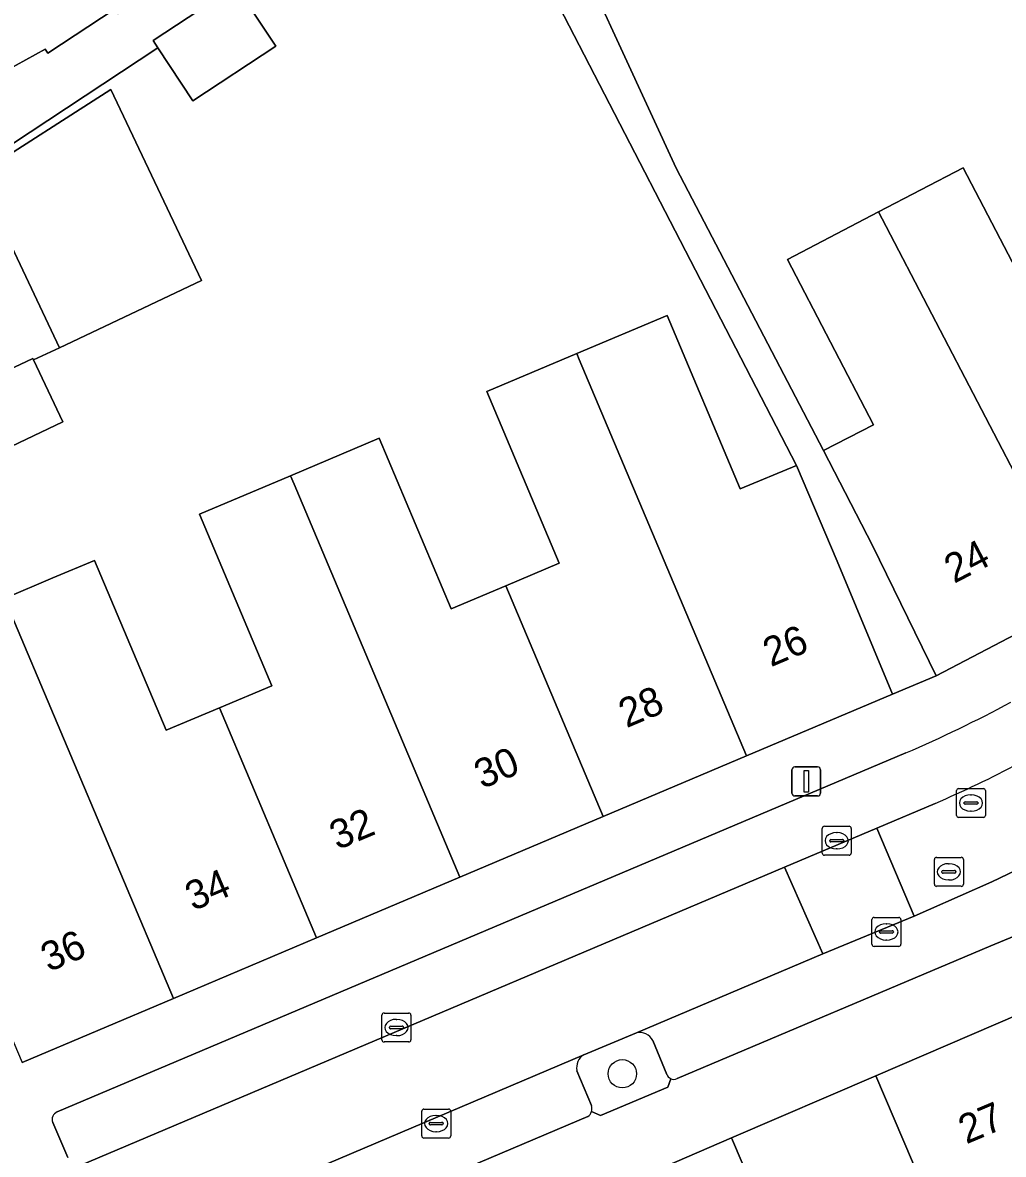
# Model space of a CAD drawing. Extents: x 159716 to 160783, y 383290 to 384031.
# Drawn here: x 160412.95 to 160446.78, y 383462.26 to 383501.29 of the extents above; entities that cross this region are included whole.
import ezdxf

# ---------------------------------------------------------------- set-up
doc = ezdxf.new("R2010")
doc.units = 0
for name, color, linetype in [('IMGEO_Boom', 7, 'Continuous'), ('IMGEO_Erf', 7, 'Continuous'), ('IMGEO_Groenvoorziening', 7, 'Continuous'), ('IMGEO_Kolk', 7, 'Continuous'), ('IMGEO_Lichtmast', 7, 'Continuous'), ('IMGEO_Pand', 7, 'Continuous'), ('IMGEO_Pand_nummerreeks', 7, 'Continuous'), ('IMGEO_Parkeervlak_open', 7, 'Continuous'), ('IMGEO_Rijbaan_lokaal_open', 7, 'Continuous'), ('IMGEO_Rioolput', 7, 'Continuous'), ('IMGEO_Voetpad_open', 7, 'Continuous')]:
    doc.layers.add(name, color=color, linetype=linetype)

msp = doc.modelspace()

# ---------------------------------------------------------------- linework, layer by layer
at = {"layer": 'IMGEO_Boom'}
msp.add_circle((160433.635, 383465.037), 0.489, dxfattribs=at)
at = {"layer": 'IMGEO_Erf'}
for points in [[(160410.053, 383498.348), (160413.731, 383500.37), (160413.822, 383500.233), (160416.145, 383501.77), (160414.883, 383503.676), (160417.563, 383505.448), (160418.824, 383503.542), (160419.035, 383503.681), (160420.163, 383504.383), (160417.766, 383508.006), (160420.889, 383510.072), (160422.04, 383508.332), (160424.811, 383510.165), (160426.163, 383508.121), (160426.24, 383508.005), (160429.356, 383510.045), (160428.037, 383512.04), (160430.525, 383513.686), (160434.534, 383516.338), (160435.854, 383514.343), (160436.792, 383514.858), (160423.195, 383534.022)], [(160430.856, 383506.328), (160435.49, 383496.267), (160440.572, 383486.539), (160442.3, 383487.42), (160439.33, 383493.124), (160442.476, 383494.762), (160445.394, 383496.282), (160448.357, 383490.591), (160450.214, 383491.558), (160451.942, 383492.458), (160448.967, 383498.17), (160452.021, 383499.746), (160452.513, 383500), (160454.934, 383501.249), (160455.587, 383500), (160457.9, 383495.572), (160459.761, 383496.541), (160461.074, 383497.224), (160458.07, 383502.859)], [(160412.323, 383481.431), (160413.995, 383482.137), (160415.428, 383482.742), (160417.902, 383476.883), (160419.742, 383477.66), (160421.544, 383478.421), (160419.047, 383484.335), (160422.19, 383485.662), (160425.252, 383486.955), (160427.734, 383481.076), (160429.617, 383481.871), (160431.455, 383482.647), (160428.958, 383488.563), (160432.064, 383489.875), (160435.177, 383491.189), (160437.698, 383485.217), (160439.641, 383486.018), (160429.533, 383505.571)], [(160420.299, 383502.563), (160421.679, 383500.478), (160418.827, 383498.592), (160417.613, 383500.427), (160411.306, 383496.264)], [(160411.39, 383496.045), (160415.995, 383498.988), (160419.12, 383492.397), (160414.221, 383490.074), (160413.329, 383489.658), (160414.343, 383487.52), (160410.518, 383485.706)]]:
    msp.add_lwpolyline(points, dxfattribs=at)
at = {"layer": 'IMGEO_Groenvoorziening'}
for points in [[(160434.119, 383466.447), (160432.306, 383465.692)], [(160435.166, 383465.011), (160434.69, 383466.181)], [(160432.07, 383465.144), (160432.575, 383463.94)], [(160432.572, 383463.735), (160432.884, 383463.6), (160435.203, 383464.573), (160435.303, 383464.868)]]:
    msp.add_lwpolyline(points, dxfattribs=at)
for centre, radius, start, end in [((160434.233, 383465.945), 0.515, 27.2902, 102.7529), ((160432.575, 383465.252), 0.516, 121.3704, 192.0307), ((160435.413, 383465.111), 0.266, 201.9501, 245.5948), ((160432.242, 383463.842), 0.347, 341.9589, 16.3642)]:
    msp.add_arc(centre, radius, start, end, dxfattribs=at)
at = {"layer": 'IMGEO_Kolk'}
for p, q in [((160440.529, 383472.649), (160440.529, 383473.501)), ((160440.604, 383473.575), (160441.456, 383473.575)), ((160441.53, 383473.501), (160441.53, 383472.649)), ((160440.788, 383473.069), (160440.788, 383473.081)), ((160440.831, 383473.118), (160441.229, 383473.118)), ((160441.017, 383473.355), (160441.042, 383473.355)), ((160441.272, 383473.081), (160441.272, 383473.069)), ((160441.226, 383473.032), (160440.828, 383473.032)), ((160441.04, 383472.795), (160441.015, 383472.795)), ((160441.456, 383472.575), (160440.604, 383472.575)), ((160442.242, 383469.503), (160442.242, 383470.355)), ((160442.317, 383470.429), (160443.169, 383470.429)), ((160443.243, 383470.355), (160443.243, 383469.503)), ((160442.544, 383469.972), (160442.942, 383469.972)), ((160442.73, 383470.209), (160442.755, 383470.209)), ((160442.501, 383469.923), (160442.501, 383469.935)), ((160442.939, 383469.886), (160442.541, 383469.886)), ((160442.753, 383469.649), (160442.728, 383469.649)), ((160442.985, 383469.935), (160442.985, 383469.923)), ((160443.169, 383469.429), (160442.317, 383469.429)), ((160425.344, 383466.207), (160425.344, 383467.059)), ((160425.419, 383467.133), (160426.271, 383467.133)), ((160425.832, 383466.913), (160425.857, 383466.913)), ((160426.345, 383467.059), (160426.345, 383466.207)), ((160425.603, 383466.627), (160425.603, 383466.639)), ((160426.041, 383466.59), (160425.643, 383466.59)), ((160425.646, 383466.676), (160426.044, 383466.676)), ((160426.087, 383466.639), (160426.087, 383466.627)), ((160426.271, 383466.133), (160425.419, 383466.133)), ((160425.855, 383466.353), (160425.83, 383466.353)), ((160426.715, 383462.893), (160426.715, 383463.745)), ((160426.79, 383463.819), (160427.642, 383463.819)), ((160427.716, 383463.745), (160427.716, 383462.893)), ((160426.974, 383463.313), (160426.974, 383463.325)), ((160427.017, 383463.362), (160427.415, 383463.362)), ((160427.203, 383463.599), (160427.228, 383463.599)), ((160427.458, 383463.325), (160427.458, 383463.313)), ((160427.412, 383463.276), (160427.014, 383463.276)), ((160427.226, 383463.039), (160427.201, 383463.039)), ((160427.642, 383462.819), (160426.79, 383462.819))]:
    msp.add_line(p, q, dxfattribs=at)
for points in [[(160440.529, 383472.649), (160440.529, 383473.501)], [(160440.604, 383473.575), (160441.456, 383473.575)], [(160441.53, 383473.501), (160441.53, 383472.649)], [(160441.456, 383472.575), (160440.604, 383472.575)], [(160442.242, 383469.503), (160442.242, 383470.355)], [(160442.317, 383470.429), (160443.169, 383470.429)], [(160443.243, 383470.355), (160443.243, 383469.503)], [(160443.169, 383469.429), (160442.317, 383469.429)], [(160425.344, 383466.207), (160425.344, 383467.059)], [(160425.419, 383467.133), (160426.271, 383467.133)], [(160426.345, 383467.059), (160426.345, 383466.207)], [(160426.271, 383466.133), (160425.419, 383466.133)], [(160426.715, 383462.893), (160426.715, 383463.745)], [(160426.79, 383463.819), (160427.642, 383463.819)], [(160427.716, 383463.745), (160427.716, 383462.893)], [(160427.642, 383462.819), (160426.79, 383462.819)]]:
    msp.add_lwpolyline(points, dxfattribs=at)
for centre, radius, start, end in [((160440.606, 383473.499), 0.0765, 91.552, 178.448), ((160440.606, 383473.499), 0.0765, 91.552, 178.448), ((160441.454, 383473.499), 0.0765, 1.552, 88.448), ((160441.454, 383473.499), 0.0765, 1.552, 88.448), ((160440.828, 383473.078), 0.0403, 85.8775, 175.7526), ((160441.233, 383473.08), 0.0386, 1.7309, 96.639), ((160440.825, 383473.068), 0.0366, 178.938, 274.7102), ((160441.229, 383473.075), 0.043, 264.8664, 352.4533), ((160440.606, 383472.651), 0.0765, 181.552, 268.448), ((160440.606, 383472.651), 0.0765, 181.552, 268.448), ((160441.454, 383472.651), 0.0765, 271.552, 358.448), ((160441.454, 383472.651), 0.0765, 271.552, 358.448), ((160442.319, 383470.353), 0.0765, 91.552, 178.448), ((160442.319, 383470.353), 0.0765, 91.552, 178.448), ((160443.167, 383470.353), 0.0765, 1.552, 88.448), ((160443.167, 383470.353), 0.0765, 1.552, 88.448), ((160442.541, 383469.932), 0.0403, 85.8775, 175.7526), ((160442.946, 383469.934), 0.0386, 1.7309, 96.639), ((160442.538, 383469.922), 0.0366, 178.938, 274.7102), ((160442.942, 383469.929), 0.043, 264.8664, 352.4533), ((160442.319, 383469.505), 0.0765, 181.552, 268.448), ((160442.319, 383469.505), 0.0765, 181.552, 268.448), ((160443.167, 383469.505), 0.0765, 271.552, 358.448), ((160443.167, 383469.505), 0.0765, 271.552, 358.448), ((160425.421, 383467.057), 0.0765, 91.552, 178.448), ((160425.421, 383467.057), 0.0765, 91.552, 178.448), ((160426.269, 383467.057), 0.0765, 1.552, 88.448), ((160426.269, 383467.057), 0.0765, 1.552, 88.448), ((160425.643, 383466.636), 0.0403, 85.8775, 175.7526), ((160425.64, 383466.626), 0.0366, 178.938, 274.7102), ((160426.044, 383466.633), 0.043, 264.8664, 352.4533), ((160426.048, 383466.638), 0.0386, 1.7309, 96.639), ((160425.421, 383466.209), 0.0765, 181.552, 268.448), ((160425.421, 383466.209), 0.0765, 181.552, 268.448), ((160426.269, 383466.209), 0.0765, 271.552, 358.448), ((160426.269, 383466.209), 0.0765, 271.552, 358.448), ((160426.792, 383463.743), 0.0765, 91.552, 178.448), ((160426.792, 383463.743), 0.0765, 91.552, 178.448), ((160427.64, 383463.743), 0.0765, 1.552, 88.448), ((160427.64, 383463.743), 0.0765, 1.552, 88.448), ((160427.014, 383463.322), 0.0403, 85.8775, 175.7526), ((160427.419, 383463.324), 0.0386, 1.7309, 96.639), ((160427.011, 383463.312), 0.0366, 178.938, 274.7102), ((160427.415, 383463.319), 0.043, 264.8664, 352.4533), ((160426.792, 383462.895), 0.0765, 181.552, 268.448), ((160426.792, 383462.895), 0.0765, 181.552, 268.448), ((160427.64, 383462.895), 0.0765, 271.552, 358.448), ((160427.64, 383462.895), 0.0765, 271.552, 358.448)]:
    msp.add_arc(centre, radius, start, end, dxfattribs=at)
for centre, major_axis, ratio, start_param, end_param in [((160441.016, 383473.075), (-0.387, 0.002), 0.722429, 4.712389, 7.853982), ((160441.041, 383473.075), (-0.39, 0.002), 0.717154, 1.570796, 4.712389), ((160442.729, 383469.929), (-0.387, 0.002), 0.722429, 4.712389, 7.853982), ((160442.754, 383469.929), (-0.39, 0.002), 0.717154, 1.570796, 4.712389), ((160425.831, 383466.633), (-0.387, 0.002), 0.722429, 4.712389, 7.853982), ((160425.856, 383466.633), (-0.39, 0.002), 0.717154, 1.570796, 4.712389), ((160427.202, 383463.319), (-0.387, 0.002), 0.722429, 4.712389, 7.853982), ((160427.227, 383463.319), (-0.39, 0.002), 0.717154, 1.570796, 4.712389)]:
    msp.add_ellipse(centre, major_axis=major_axis, ratio=ratio, start_param=start_param, end_param=end_param, dxfattribs=at)
at = {"layer": 'IMGEO_Lichtmast'}
for p, q in [((160439.481, 383474.719), (160439.481, 383475.519)), ((160439.481, 383475.519), (160439.481, 383474.719)), ((160439.581, 383475.619), (160440.371, 383475.619)), ((160440.371, 383475.619), (160439.581, 383475.619)), ((160440.471, 383475.519), (160440.471, 383474.719)), ((160440.471, 383474.719), (160440.471, 383475.519)), ((160440.371, 383474.619), (160439.581, 383474.619)), ((160439.581, 383474.619), (160440.371, 383474.619))]:
    msp.add_line(p, q, dxfattribs=at)
msp.add_lwpolyline([(160439.901, 383475.494), (160440.051, 383475.494), (160440.051, 383474.744), (160439.901, 383474.744), (160439.901, 383475.494)], dxfattribs=at)
for centre, start, end in [((160439.581, 383475.519), 90, 180), ((160439.581, 383475.519), 90, 180), ((160440.371, 383475.519), 0, 90), ((160440.371, 383475.519), 360, 90), ((160439.581, 383474.719), 180, 270), ((160439.581, 383474.719), 180, 270), ((160440.371, 383474.719), 270, 0), ((160440.371, 383474.719), 270, 0)]:
    msp.add_arc(centre, 0.1, start, end, dxfattribs=at)
at = {"layer": 'IMGEO_Pand'}
for points in [[(160420.299, 383502.563), (160417.448, 383500.677), (160417.613, 383500.427), (160418.827, 383498.592), (160421.679, 383500.478)], [(160411.39, 383496.045), (160414.221, 383490.074), (160419.12, 383492.397), (160415.995, 383498.988)], [(160450.214, 383491.558), (160448.357, 383490.591), (160445.394, 383496.282), (160442.476, 383494.762), (160442.599, 383494.526), (160449.448, 383481.371), (160454.219, 383483.867)], [(160442.599, 383494.526), (160442.476, 383494.762), (160439.33, 383493.124), (160442.3, 383487.42), (160440.572, 383486.539), (160442.259, 383483.26), (160444.456, 383478.761), (160449.448, 383481.371)], [(160439.641, 383486.018), (160437.698, 383485.217), (160435.177, 383491.189), (160432.064, 383489.875), (160432.152, 383489.667), (160437.922, 383476.001), (160442.949, 383478.128), (160441.044, 383482.714)], [(160432.152, 383489.667), (160432.064, 383489.875), (160428.958, 383488.563), (160431.455, 383482.647), (160429.617, 383481.871), (160432.979, 383473.909), (160437.922, 383476.001)], [(160413.329, 383489.658), (160413.304, 383489.711), (160409.479, 383487.897), (160410.518, 383485.706), (160414.343, 383487.52)], [(160429.617, 383481.871), (160427.734, 383481.076), (160425.252, 383486.955), (160422.19, 383485.662), (160422.314, 383485.368), (160428.035, 383471.817), (160432.979, 383473.909)], [(160422.314, 383485.368), (160422.19, 383485.662), (160419.047, 383484.335), (160421.544, 383478.421), (160419.742, 383477.66), (160423.092, 383469.726), (160428.035, 383471.817)], [(160419.742, 383477.66), (160417.902, 383476.883), (160415.428, 383482.742), (160413.995, 383482.137), (160412.323, 383481.431), (160418.149, 383467.634), (160423.092, 383469.726)], [(160412.323, 383481.431), (160409.388, 383480.191), (160411.839, 383474.387), (160409.537, 383473.422), (160412.932, 383465.426), (160418.149, 383467.634)], [(160447.343, 383467.106), (160442.373, 383464.964), (160445.87, 383456.765), (160447.814, 383457.594), (160450.146, 383452.125), (160453.18, 383453.418)], [(160442.373, 383464.964), (160437.405, 383462.822), (160443.225, 383449.175), (160446.457, 383450.553), (160444.125, 383456.021), (160445.87, 383456.765)], [(160437.405, 383462.822), (160432.435, 383460.679), (160435.948, 383452.441), (160437.943, 383453.292), (160440.272, 383447.829), (160443.256, 383449.102), (160443.225, 383449.175)]]:
    msp.add_lwpolyline(points, close=True, dxfattribs=at)
at = {"layer": 'IMGEO_Parkeervlak_open'}
for points in [[(160443.414, 383476.101), (160414.146, 383463.719)], [(160414.256, 383461.59), (160439.234, 383472.166), (160442.414, 383473.513), (160444.425, 383474.364)], [(160450.686, 383473.825), (160448.326, 383472.59), (160446.383, 383471.66), (160444.194, 383470.688), (160443.698, 383470.478), (160440.546, 383469.169), (160434.119, 383466.447)], [(160435.53, 383464.871), (160446.34, 383469.449), (160447.487, 383469.926), (160448.781, 383470.565), (160450.997, 383471.726)], [(160434.69, 383466.181), (160435.166, 383465.011)], [(160432.306, 383465.692), (160420.476, 383460.662)], [(160432.575, 383463.94), (160432.07, 383465.144)], [(160413.989, 383463.356), (160414.506, 383462.153)], [(160421.908, 383459.097), (160432.448, 383463.559)]]:
    msp.add_lwpolyline(points, dxfattribs=at)
for centre, radius, start, end in [((160423.943, 383521.012), 48.95, 293.4389, 298.1502), ((160427.937, 383512.547), 41.591, 293.3559, 297.778), ((160434.233, 383465.945), 0.515, 27.2902, 102.7529), ((160432.575, 383465.252), 0.516, 121.3704, 192.0307), ((160435.413, 383465.111), 0.266, 201.9501, 245.5948), ((160435.413, 383465.109), 0.265, 245.4303, 296.084), ((160414.244, 383463.461), 0.276, 110.8719, 202.3504), ((160432.242, 383463.836), 0.345, 306.673, 342.9941), ((160432.242, 383463.842), 0.347, 341.9589, 16.3642)]:
    msp.add_arc(centre, radius, start, end, dxfattribs=at)
at = {"layer": 'IMGEO_Rijbaan_lokaal_open'}
msp.add_lwpolyline([(160444.425, 383474.364), (160442.414, 383473.513), (160443.698, 383470.478), (160444.194, 383470.688), (160446.383, 383471.66), (160448.326, 383472.59), (160450.686, 383473.825), (160452.428, 383474.705), (160468.689, 383483.205), (160470.424, 383484.097), (160475.827, 383486.951), (160477.633, 383487.98), (160479.723, 383489.166), (160486.172, 383493.171)], dxfattribs=at)
for points in [[(160442.414, 383473.513), (160439.234, 383472.166), (160440.546, 383469.169), (160443.698, 383470.478)], [(160413.413, 383457.726), (160414.355, 383458.079), (160415.032, 383458.338), (160419.59, 383460.282), (160420.476, 383460.662), (160432.306, 383465.692), (160434.119, 383466.447), (160440.546, 383469.169), (160439.234, 383472.166), (160414.256, 383461.59), (160411.383, 383460.426), (160408.637, 383459.367), (160406.976, 383458.771), (160391.978, 383453.269), (160378.421, 383448.278), (160373.951, 383446.647), (160375.101, 383443.604), (160376.222, 383444.022), (160377.682, 383444.533), (160394.918, 383450.857), (160396.309, 383451.338)]]:
    msp.add_lwpolyline(points, close=True, dxfattribs=at)
msp.add_arc((160427.937, 383512.547), 41.591, 293.3559, 297.778, dxfattribs=at)
at = {"layer": 'IMGEO_Rioolput'}
for p, q in [((160445.16, 383473.95), (160445.16, 383474.802)), ((160445.235, 383474.876), (160446.087, 383474.876)), ((160445.648, 383474.656), (160445.673, 383474.656)), ((160446.161, 383474.802), (160446.161, 383473.95)), ((160445.419, 383474.37), (160445.419, 383474.382)), ((160445.857, 383474.333), (160445.459, 383474.333)), ((160445.462, 383474.419), (160445.86, 383474.419)), ((160445.903, 383474.382), (160445.903, 383474.37)), ((160446.087, 383473.876), (160445.235, 383473.876)), ((160445.671, 383474.096), (160445.646, 383474.096)), ((160444.397, 383471.576), (160444.397, 383472.428)), ((160444.472, 383472.502), (160445.324, 383472.502)), ((160445.398, 383472.428), (160445.398, 383471.576)), ((160444.656, 383471.996), (160444.656, 383472.008)), ((160445.094, 383471.959), (160444.696, 383471.959)), ((160444.699, 383472.045), (160445.097, 383472.045)), ((160444.885, 383472.282), (160444.91, 383472.282)), ((160445.14, 383472.008), (160445.14, 383471.996)), ((160444.908, 383471.722), (160444.883, 383471.722)), ((160445.324, 383471.502), (160444.472, 383471.502))]:
    msp.add_line(p, q, dxfattribs=at)
for points in [[(160445.16, 383473.95), (160445.16, 383474.802)], [(160445.235, 383474.876), (160446.087, 383474.876)], [(160446.161, 383474.802), (160446.161, 383473.95)], [(160446.087, 383473.876), (160445.235, 383473.876)], [(160444.397, 383471.576), (160444.397, 383472.428)], [(160444.472, 383472.502), (160445.324, 383472.502)], [(160445.398, 383472.428), (160445.398, 383471.576)], [(160445.324, 383471.502), (160444.472, 383471.502)]]:
    msp.add_lwpolyline(points, dxfattribs=at)
for centre, radius, start, end in [((160445.237, 383474.8), 0.0765, 91.552, 178.448), ((160445.237, 383474.8), 0.0765, 91.552, 178.448), ((160446.085, 383474.8), 0.0765, 1.552, 88.448), ((160446.085, 383474.8), 0.0765, 1.552, 88.448), ((160445.459, 383474.379), 0.0403, 85.8775, 175.7526), ((160445.456, 383474.369), 0.0366, 178.938, 274.7102), ((160445.86, 383474.376), 0.043, 264.8664, 352.4533), ((160445.864, 383474.381), 0.0386, 1.7309, 96.639), ((160445.237, 383473.952), 0.0765, 181.552, 268.448), ((160445.237, 383473.952), 0.0765, 181.552, 268.448), ((160446.085, 383473.952), 0.0765, 271.552, 358.448), ((160446.085, 383473.952), 0.0765, 271.552, 358.448), ((160444.474, 383472.426), 0.0765, 91.552, 178.448), ((160444.474, 383472.426), 0.0765, 91.552, 178.448), ((160445.322, 383472.426), 0.0765, 1.552, 88.448), ((160445.322, 383472.426), 0.0765, 1.552, 88.448), ((160444.696, 383472.005), 0.0403, 85.8775, 175.7526), ((160444.693, 383471.995), 0.0366, 178.938, 274.7102), ((160445.097, 383472.002), 0.043, 264.8664, 352.4533), ((160445.101, 383472.007), 0.0386, 1.7309, 96.639), ((160444.474, 383471.578), 0.0765, 181.552, 268.448), ((160444.474, 383471.578), 0.0765, 181.552, 268.448), ((160445.322, 383471.578), 0.0765, 271.552, 358.448), ((160445.322, 383471.578), 0.0765, 271.552, 358.448)]:
    msp.add_arc(centre, radius, start, end, dxfattribs=at)
for centre, major_axis, ratio, start_param, end_param in [((160445.647, 383474.376), (-0.387, 0.002), 0.722429, 4.712389, 7.853982), ((160445.672, 383474.376), (-0.39, 0.002), 0.717154, 1.570796, 4.712389), ((160444.884, 383472.002), (-0.387, 0.002), 0.722429, 4.712389, 7.853982), ((160444.909, 383472.002), (-0.39, 0.002), 0.717154, 1.570796, 4.712389)]:
    msp.add_ellipse(centre, major_axis=major_axis, ratio=ratio, start_param=start_param, end_param=end_param, dxfattribs=at)
at = {"layer": 'IMGEO_Voetpad_open'}
for points in [[(160423.195, 383534.022), (160436.792, 383514.858), (160435.854, 383514.343), (160431.844, 383511.691), (160429.356, 383510.045), (160426.24, 383508.005), (160423.469, 383506.171), (160423.389, 383506.292), (160420.266, 383504.227), (160420.163, 383504.383), (160419.035, 383503.681), (160418.824, 383503.542), (160418.941, 383503.365), (160416.262, 383501.593), (160416.145, 383501.77), (160413.822, 383500.233), (160413.731, 383500.37), (160410.053, 383498.348)], [(160432.435, 383460.679), (160437.405, 383462.822), (160442.373, 383464.964), (160447.343, 383467.106), (160452.408, 383469.29), (160453.253, 383469.701), (160457.967, 383472.21), (160462.733, 383474.747), (160467.502, 383477.285), (160472.268, 383479.822), (160477.037, 383482.36), (160478.241, 383483.001), (160480.377, 383484.144), (160482.026, 383485.026), (160482.856, 383485.488), (160487.383, 383488.318), (160491.982, 383491.194), (160496.58, 383494.069), (160501.178, 383496.945), (160505.777, 383499.821), (160510.513, 383502.782), (160513.025, 383504.314), (160521.892, 383510.886), (160528.836, 383516.141)], [(160429.533, 383505.571), (160439.641, 383486.018), (160441.044, 383482.714), (160442.949, 383478.128), (160444.456, 383478.761), (160442.259, 383483.26), (160440.572, 383486.539), (160435.49, 383496.267), (160430.856, 383506.328)], [(160411.306, 383496.264), (160417.613, 383500.427), (160417.448, 383500.677), (160420.299, 383502.563)], [(160479.491, 383497.62), (160474.684, 383494.636), (160473.336, 383493.858), (160472.662, 383493.507), (160468.533, 383491.353), (160468.365, 383491.265), (160463.761, 383488.857), (160458.991, 383486.362), (160454.219, 383483.867), (160449.448, 383481.371), (160444.456, 383478.761), (160442.949, 383478.128), (160437.922, 383476.001), (160432.979, 383473.909), (160428.035, 383471.817), (160423.092, 383469.726), (160418.149, 383467.634), (160412.932, 383465.426)], [(160409.479, 383487.897), (160413.304, 383489.711), (160413.329, 383489.658), (160414.221, 383490.074), (160411.39, 383496.045)], [(160414.146, 383463.719), (160443.414, 383476.101)], [(160450.997, 383471.726), (160448.781, 383470.565), (160447.487, 383469.926), (160446.34, 383469.449), (160435.53, 383464.871)], [(160435.303, 383464.868), (160435.203, 383464.573), (160432.884, 383463.6), (160432.572, 383463.735)], [(160414.506, 383462.153), (160413.989, 383463.356)], [(160432.448, 383463.559), (160421.908, 383459.097)]]:
    msp.add_lwpolyline(points, dxfattribs=at)
for centre, radius, start, end in [((160423.943, 383521.012), 48.95, 293.4389, 298.1502), ((160435.413, 383465.109), 0.265, 245.4303, 296.084), ((160414.244, 383463.461), 0.276, 110.8719, 202.3504), ((160432.242, 383463.836), 0.345, 306.673, 342.9941)]:
    msp.add_arc(centre, radius, start, end, dxfattribs=at)

# ---------------------------------------------------------------- texts
at = {"layer": 'IMGEO_Pand_nummerreeks'}
for s, rotation, p in [('24', 27.5077, (160445.077, 383481.931)), ('26', 22.8897, (160438.757, 383479.055)), ('28', 22.8897, (160433.778, 383476.952)), ('30', 22.8897, (160428.797, 383474.849)), ('32', 22.8897, (160423.809, 383472.743)), ('34', 22.8897, (160418.83, 383470.641)), ('36', 22.8897, (160413.849, 383468.537)), ('27', 22.8667, (160445.499, 383462.6))]:
    msp.add_text(s, height=1, rotation=rotation, dxfattribs=at).set_placement(p)

doc.saveas('drawing.dxf')
